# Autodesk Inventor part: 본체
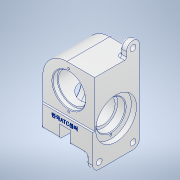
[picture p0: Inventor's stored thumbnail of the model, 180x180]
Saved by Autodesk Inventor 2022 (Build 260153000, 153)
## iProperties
Created: 2023-09
Part Number: 본체
Material: 알루미늄 6061
Document SubType Name: Modeling
Designer: PC-13
Density: 2.7 g/cm^3
Appearance: 알루미늄 - 평지
Mass: 944.108 g
Surface Area: 630.513 cm^2
Volume: 349.669 cm^3
Author: PC-13
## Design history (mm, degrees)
sketch "스케치1"
  geometry: L1 (-56, 0)-(56, 0) reference; L2 (0, -74.2)-(0, 74.2) reference; L3 (-40, 53)-(-40, -53); L4 (-40, -53)-(40, -53); L5 (40, -53)-(40, 53); L6 (40, 53)-(-40, 53); 1 further point
  constraints: 8 end point, 3 perpendicular, 1 vertical, 2 other
  dimensions: "d0" = 80 distance of L5.end L3.start; "d1" = 106 distance of L3.start L3.end
extrude "돌출1" new body sketch "스케치1" stored distance "d2" = 72; taper "d3" = 0 deg
fillet "모깎기1" dims "d4" = 37
sketch "스케치2"
  geometry: L1 (0, -74.2)-(0, 74.2) reference; L2 (-56, 0)-(56, 0) reference; L3 (40, -53)-(40, 53) reference; L4 (40, -53)-(40, -73); L5 (40, -73)-(30, -73); L6 (30, -73)-(30, -53); L7 (-40, -53)-(40, -53) reference; L8 (30, -53)-(40, -53); 1 further point
  constraints: 8 end point, 2 perpendicular, 1 collinear, 1 point on line, 1 vertical
  dimensions: "d5" = 10 distance of L4.end L5.end; "d6" = 20 distance of L3.start L4.end
extrude "돌출2" join sketch "스케치2" distance "d7" = 72; taper "d8" = 0 deg
sketch "스케치3"
  geometry: L1 (86.4, -53)-(-14.4, -53) reference; L2 (36, -155.2)-(36, 49.2) reference; L3 (72, 0)-(0, 0) reference; L4 (72, 0)-(72, 20); L5 (72, 20)-(52, 20); L6 (52, 20)-(52, 0); L7 (52, 0)-(72, 0); 1 further point
  constraints: 8 end point, 2 perpendicular, 1 collinear, 1 point on line, 1 vertical
  dimensions: "d9" = 20 distance of L4.end L5.end; "d10" = 20 distance of L3.start L4.end
extrude "돌출3" join sketch "스케치3" distance "d11" = 10; taper "d12" = 0 deg
sketch "스케치4"
  geometry: L1 (36, -29.2)-(36, 175.2) reference; L2 (86.4, 73)-(-14.4, 73) reference; L3 (0, 0)-(0, 126) reference; L4 (0, 126)-(3, 126); L5 (52, 126)-(0, 126) reference; L6 (3, 126)-(3, 54); L7 (3, 54)-(0, 54); L8 (0, 54)-(0, 126); 2 further points
  constraints: 8 end point, 3 perpendicular, 1 point on line
  dimensions: "d13" = 3 distance of L3.end L4.end; "d14" = 72 distance of L4.end L6.end
extrude "돌출4" cut sketch "스케치4" distance "d15" = 80; taper "d16" = 0 deg
fillet "모깎기2" dims "d17" = 10
fillet "모깎기3" dims "d18" = 10
sketch "스케치5"
  geometry: A1 r 10 centre (-62, 10) between (-52, 10) and (-72, 10) reference; 2 further points
  constraints: 1 coincident
hole "구멍1" sketch "스케치5" at (-62, 10) diameter "d19" = 9; stored, may be unused: countersink angle "d23" = 90 deg, drill point angle "d25" = 118 deg; dims "d20" = 6, "d21" = 4, "d22" = 2, "d24" = 8
sketch "스케치6"
  geometry: A1 r 10 centre (10, -10) between (0, -10) and (10, -20) reference; 2 further points
  constraints: 1 coincident
hole "구멍2" sketch "스케치6" at (10, -10) diameter "d26" = 9; stored, may be unused: countersink angle "d30" = 90 deg, drill point angle "d32" = 118 deg; dims "d27" = 6, "d28" = 4, "d29" = 2, "d31" = 8
sketch "스케치7"
  geometry: A1 r 10 centre (62, -10) between (62, -20) and (72, -10) reference; 2 further points
  constraints: 1 coincident
hole "구멍3" sketch "스케치7" at (62, -10) diameter "d33" = 9; stored, may be unused: countersink angle "d37" = 90 deg, drill point angle "d39" = 118 deg; dims "d34" = 6, "d35" = 4, "d36" = 2, "d38" = 8
sketch "스케치8"
  geometry: L1 (-56, 0)-(56, 0) reference; L2 (0, -102.2)-(0, 102.2) reference; L3 (30, -53)-(-40, -53) reference; L4 (-11, -53)-(-11, -33); L5 (-11, -33)-(5, -33); L6 (5, -33)-(5, -53); L7 (-11, -53)-(5, -53); L8 (40, -63)-(40, -19) reference; 1 further point
  constraints: 8 end point, 2 perpendicular, 2 point on line, 1 collinear, 1 vertical
  dimensions: "d40" = 16 distance of L4.end L5.end; "d41" = 20 distance of L5.end L6.end; "d42" = 51 distance between parallel lines of L4 L8
extrude "돌출5" cut sketch "스케치8" distance "d43" = 72; taper "d44" = 0 deg
sketch "스케치9"
  geometry: L1 (0, -50.4)-(0, 50.4) reference; L2 (-102.2, 0)-(102.2, 0) reference; L3 (16, 45.509)-(16, -53.175); L4 (-53, -36)-(-53, 36) reference; L5 (16, 33)-(53, 33) reference; L6 (41, 33)-(41, 26); L7 (41, 26)-(39, 26); L8 (39, 26)-(39, -14); L9 (39, -14)-(34.5, -14); L10 (33.5, -15)-(33.5, -28.7); L11 (33.2, -29)-(31.5, -29); L12 (31.5, -29)-(31.5, -30); L13 (28.5, -33)-(16, -33); L14 (16, -36)-(16, 33) reference; L15 (41, 33)-(16, 33); L16 (34.5, -14)-(33.5, -15); A1 r 3 centre (28.5, -30) between (28.5, -33) and (31.5, -30); A2 r 0.3 centre (33.2, -28.7) between (33.2, -29) and (33.5, -28.7); 5 further points
  constraints: 22 end point, 9 perpendicular, 8 point on line, 4 point on circle, 4 tangent, 2 centre point, 1 vertical
  dimensions: "d45" = 69 distance between parallel lines of L3 L4; "d46" = 50 diameter of L6 L3; "d47" = 46 diameter of L8 L3; "d48" = 35 diameter of L10 L3; "d49" = 31 diameter of L12 L3; "d50" = 7 distance of L6.start L6.end; "d51" = 40 distance of L7.end L8.end; "d52" = 15 distance of point (33.5, -14) point (33.5, -29); "d53" = 4 distance of L11.end point (31.5, -33); "d54" = 3 radius of A1; "d55" = 0.3 radius of A2; "d56" = 1 distance of L9.end point (33.5, -14); "d57" = 1 distance of L10.start point (33.5, -14) (= d56)
revolve "회전1" sketch "스케치9" stored, may be unused: angle "d58" = 90 deg
chamfer "모따기1" distance "d59" = 1; stored, may be unused: second distance "d60" = 2, angle "d61" = 45 deg
sketch "스케치11"
  geometry: L1 (-61.984, -18)-(81.394, -18); L2 (-11, -53)-(-40, -53) reference; L3 (-25, -40.5)-(-25, -36.5); L4 (-25, -36.5)-(20, -36.5); L5 (20, -36.5)-(20, -40.5); L6 (20, -40.5)-(31, -40.5); L7 (32, -41.5)-(32, -49.5); L8 (32, -49.5)-(40, -49.5); L9 (40, -63)-(40, 63) reference; L10 (-25, -40.5)-(-36, -40.5); L11 (-37, -41.5)-(-37, -49.5); L12 (-37, -49.5)-(-40, -49.5); L13 (-40, -53)-(-40, 16) reference; L14 (-40, -49.5)-(-40, -18.5); L15 (40, -49.5)-(40, -18); L16 (-37, -41.5)-(-36, -40.5); L17 (32, -41.5)-(31, -40.5); 4 further points
  constraints: 28 end point, 8 point on line, 5 perpendicular, 4 horizontal, 1 midpoint
  dimensions: "d62" = 35 distance between parallel lines of L1 L2; "d63" = 3 distance of L11.end L12.end; "d64" = 12 distance of L3.start point (-37, -40.5); "d65" = 12 distance of L5.end point (32, -40.5); "d66" = 8 distance of L7.end L8.end; "d68" = 63 diameter of L12 L1; "d69" = 45 diameter of L10 L1; "d70" = 37 diameter of L4 L1; "d71" = 45 diameter of L6 L1; "d72" = 63 diameter of L8 L1; "d73" = 1 distance of L11.start point (-37, -40.5); "d74" = 1 distance of L10.end point (-37, -40.5) (= d73); "d75" = 1 distance of L7.start point (32, -40.5) (= d73); "d76" = 1 distance of L6.end point (32, -40.5) (= d75)
revolve "회전2" sketch "스케치11" stored, may be unused: angle "d77" = 90 deg
fillet "모깎기4" dims "d78" = 3
fillet "모깎기5" dims "d79" = 3
fillet "모깎기6" dims "d80" = 3
sketch "스케치13"
  geometry: L1 (-37, -53)-(-11, -53) reference; L2 (40, -63)-(40, -19) reference; 2 further points
  constraints: 1 other
  dimensions: "d81" = 27 distance from line of L1 point (-3, -26); "d82" = 43 distance from line of L2 point (-3, -26)
feature "엠보싱1" sketch "스케치13" dims "d83" = 0.5, "d84" = 0
sketch "스케치14"
  geometry: L1 (0, -84.2)-(0, 120.2) reference; L2 (-50.5, 18)-(51, 18) reference; C1 r 22.5 at (0, 0) reference; A1 r 26 centre (0, 0) between (0, 26) and (0, -26); 1 further point
  constraints: 2 point on circle, 1 centre point, 1 coincident
  dimensions: "d86" = 52 diameter of A1; "d87" = 8 distance from line of L2 A1.start; "d88" = 44 distance from line of L2 A1.end
hole "구멍4" sketch "스케치14" at (0, 26), (0, -26) diameter "d89" = 3.242; stored, may be unused: countersink angle "d93" = 90 deg, drill point angle "d95" = 118 deg; dims "d90" = 8, "d91" = 4, "d92" = 2, "d94" = 10
sketch "스케치15"
  geometry: L1 (60.501, 18)-(-111.006, 18) reference; L2 (0, -84.2)-(0, 120.2) reference; A1 r 26 centre (0, 0) between (0, 26) and (0, -26); 1 further point
  constraints: 3 point on line, 2 point on circle, 1 centre point
  dimensions: "d96" = 52 diameter of A1; "d97" = 18 distance from line of L1 A1.centre
hole "구멍5" sketch "스케치15" at (0, 26), (0, -26) diameter "d98" = 3.242; stored, may be unused: countersink angle "d102" = 90 deg, drill point angle "d104" = 118 deg; dims "d99" = 8, "d100" = 4, "d101" = 2, "d103" = 10
sketch "스케치16"
  geometry: L1 (-96, 19)-(16, 19) reference; L2 (-40, -83.2)-(-40, 121.2) reference; C1 r 12.5 at (-40, 35) reference; A1 r 29 centre (-40, 35) between (-40, 64) and (-40, 6); 1 further point
  constraints: 2 point on circle, 2 point on line, 1 centre point, 1 coincident
  dimensions: "d105" = 58 diameter of A1
hole "구멍6" sketch "스케치16" at (-40, 64), (-40, 6) diameter "d106" = 3.242; stored, may be unused: countersink angle "d110" = 90 deg, drill point angle "d112" = 118 deg; dims "d107" = 8, "d108" = 4, "d109" = 2, "d111" = 10
sketch "스케치17"
  geometry: L1 (-26, -72)-(0, -72) reference; L2 (16, -3)-(16, -69) reference; 3 further points
  dimensions: "d113" = 50 distance of point (8, -61) point (8, -11); "d114" = 11 distance from line of L1 point (8, -61); "d115" = 8 distance from line of point (8, -11) L2; "d116" = 8 distance from line of L2 point (8, -61)
hole "구멍7" sketch "스케치17" at (8, -11), (8, -61) diameter "d117" = 3.242; stored, may be unused: countersink angle "d121" = 90 deg, drill point angle "d123" = 118 deg; dims "d118" = 8, "d119" = 4, "d120" = 2, "d122" = 10
node "솔리드1"
feature "A9D066F2-1C7D-4E18-AEED-F7BC21143FA4" dims "d19" = 9, "d20" = 6, "d21" = 4, "d22" = 2, "d23" = 90 deg, "d24" = 8, "d25" = 118 deg
